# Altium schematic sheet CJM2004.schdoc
size 127 x 101 mm
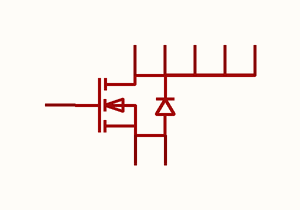
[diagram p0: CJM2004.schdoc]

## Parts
Q?  cjm2004  [DFNWB-6_L2.0-W2.0-P0.65-BL-EP_CJM1206]  (value not drawn)

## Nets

Not connected (* = marked no-connect by the designer): Q? 1(D) 2(D) 3(G) 4(S) 5(D) 6(D) 7(D) 8(S)

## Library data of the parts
Q? = cjm2004: 数量:1个N沟道;漏源电压(Vdss):20V;连续漏极电流(Id):15A;导通电阻(RDS(on)):6mΩ@4.5V;耗散功率(Pd):-;阈值电压(Vgs(th)):500mV;; Manufacturer: CJ(江苏长电/长晶); AddInBom: yes; ModelId: 5056914cf65749c482db2a177f5f110e; ModelName: DFNWB-6_L2.0-W2.0-H0.8-P0.65-BL-EP_CJM1206; ModelTransform: 79.527,79.527,0,0,0,0,0,0.002,0; Number: 1个N沟道; Drain to Source Voltage: 20V; Current - Continuous Drain(Id): 15A; Gate Threshold Voltage (Vgs(th)): 500mV; Gate Charge(Qg): 17nC@4.5V; Input Capacitance(Ciss): 1.85nF; Reverse Transfer Capacitance (Crss@Vds): 210pF; Type: N沟道; Output Capacitance(Coss): 250pF; Vgs: ±10V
